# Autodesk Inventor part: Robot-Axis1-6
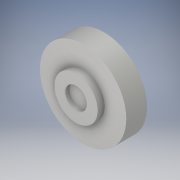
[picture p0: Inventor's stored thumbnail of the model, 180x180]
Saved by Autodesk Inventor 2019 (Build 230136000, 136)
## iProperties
Created: 2018-07
Part Number: Robot-Axis1-6
Material: Aluminum 6061
Description: 123456
Document SubType Name: Modeling
Designer: Power User
Mass: 280.594 g
Surface Area: 159.719 cm^2
Volume: 103.924 cm^3
Density: 2.7 g/cm^3
Appearance: Aluminum - Flat
Title: GEAR
Author: Power User
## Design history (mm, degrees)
sketch "Sketch6"
  geometry: C1 r 40 at (0, 0); C2 r 20 at (0, 0); 1 further point
  constraints: 2 centre point, 2 coincident
  dimensions: "d44" = 80 diameter of C1; "d45" = 40 diameter of C2
extrude "Extrusion5" new body sketch "Sketch6" distance "d46" = 19.3; taper "d47" = 0 deg
extrude "Extrusion6" join sketch "Sketch6" distance "d48" = 25.8; taper "d49" = 0 deg
sketch "Sketch7"
  geometry: C1 r 20 at (0, 0) reference; 2 further points
  constraints: 1 coincident
hole "Hole2" sketch "Sketch7" at (0, 0) diameter "d50" = 20; stored, may be unused: countersink angle "d54" = 90 deg, drill point angle "d56" = 0 deg; dims "d51" = 6, "d52" = 4, "d53" = 2, "d55" = 4
body "Solid2"
